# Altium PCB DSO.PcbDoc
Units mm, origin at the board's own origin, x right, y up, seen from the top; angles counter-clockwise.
Board outline 78.7 x 90.25 mm, 2 copper layers (Top Layer, Bottom Layer), stack 1.571 mm thick; 0 components, 80 nets, 1 pads, 0 vias.
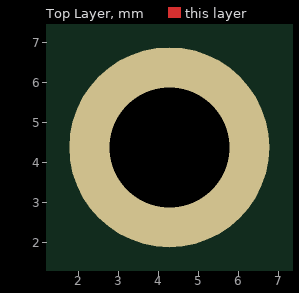
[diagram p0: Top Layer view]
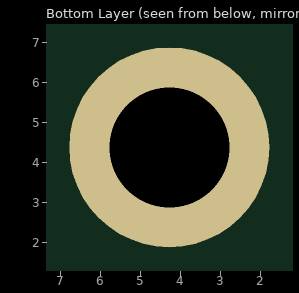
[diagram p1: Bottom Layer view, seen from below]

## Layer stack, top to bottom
Top Solder: solder mask 0.0102, Solder Resist, Dk 3.5
Top Layer: signal copper 0.0356
Dielectric1: core 1.5, FR-4, Dk 4.8
Bottom Layer: signal copper 0.0356
Bottom Solder: solder mask 0.0102, Solder Resist, Dk 3.5

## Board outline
-0.03,0.097 -0.03,90.064 cw(c0.097,90.064) 0.026,90.169 cw(c0.131,90.097) 0.131,90.225 78.54,90.225 cw(c78.54,90.097) 78.668,90.097 78.668,0.097 cw(c78.54,0.097) 78.54,-0.03 0.097,-0.03 cw(c0.097,0.097)

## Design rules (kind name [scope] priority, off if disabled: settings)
Clearance [All] p1: gap=0.254 ignorepadtopadclearanceinfootprint=FALSE except(0: Arc-Hole Track-Hole SMDPad-Hole THPad-Hole Via-Hole Fill-Hole Poly-Hole Region-Hole Text-Hole)
ComponentClearance [All] p1 off: gap=0.254 collisioncheckmode=3 verticalgap=0.254 showdistances=FALSE
DiffPairsRouting [All] p1: maxlimit=0.508 minlimit=0.254 mostfreqgap=0.254 toplayer_minwidth=0.381 toplayer_maxwidth=0.381 toplayer_prefwidth=0.381 bottomlayer_minwidth=0.381 bottomlayer_maxwidth=0.381 bottomlayer_prefwidth=0.381 maxuncoupledlength=12.7
FabricationTestPointUsage TestPointUsage [All] p1: valid=0 allowmultiple=FALSE
FabricationTestpoint Testpoint [All] p1: side=3 testpointundercomponent=TRUE minsize=1.016 maxsize=2.54 preferedsize=1.524 minholesize=0 maxholesize=1.016 preferedholesize=0.813 testpointgrid=0.025 allowsidetop=TRUE allowsidebottom=TRUE usegrid=TRUE gridtolerance=0
Height [All] p1: minheight=0 maxheight=200 prefheight=12.7
HoleSize [All] p1: absolutevalues=TRUE maxlimit=5.055 minlimit=0.381 maxpercent=80.000 minpercent=20.000
MinimumAnnularRing [All] p1: minimumring=0.127
PolygonConnect PolygonConnect_2 [(ObjectKind = 'Via') vs IsNamedPolygon('Bottom Layer-No Net') Or  IsNamedPolygon('Top Power') Or  IsNamedPolygon('TOP MCU VCC') Or  IsNamedPolygon('Top Analog') Or  IsNamedPolygon('Top USB') Or  IsNamedPolygon('Top Digital') Or  IsNamedPolygon('Top RAM VCC') Or  IsNamedPolygon('Bottom Power') Or  IsNamedPolygon('Bottom Analog') Or  IsNamedPolygon('Bottom Digital')] p1: connectstyle=Direct reliefconductorwidth=0.254 reliefentries=4 polygonreliefangle="90 Angle" airgapwidth=0.254
PolygonConnect PolygonConnect_1 [(ObjectKind = 'Via')] p2 off: connectstyle=Direct reliefconductorwidth=0.254 reliefentries=4 polygonreliefangle="90 Angle" airgapwidth=0.254
PolygonConnect [All] p3 off: connectstyle=Relief reliefconductorwidth=0.254 reliefentries=4 polygonreliefangle="90 Angle" airgapwidth=0.254
RoutingVias [All] p1: holewidth=0.381 width=0.635 viastyle="Through Hole" minholewidth=0.381 minwidth=0.635 maxholewidth=2.032 maxwidth=2.54
SilkToSolderMaskClearance SilkscreenOverComponentPads [IsPad] p1: minsilkscreentomaskgap=0.254 clearancetoexposedcopper=TRUE
SolderMaskExpansion [All] p1: expansion=0.152
Width [All] p1: maxlimit=25.4 minlimit=0.152 preferedwidth=0.254 minimp=50.000000 maximp=50.000000 favimp=50.000000
23 further rules are at their usual default settings.

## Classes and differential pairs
net class ADC_D[0..7]: ADC_D0 ADC_D1 ADC_D2 ADC_D3 ADC_D4 ADC_D5 ADC_D6 ADC_D7
net class ADC_A[0..15]: ADC_A0 ADC_A1 ADC_A2 ADC_A3 ADC_A4 ADC_A5 ADC_A6 ADC_A7 ADC_A8 ADC_A9 ADC_A10 ADC_A11 ADC_A12 ADC_A13 ADC_A14 ADC_A15

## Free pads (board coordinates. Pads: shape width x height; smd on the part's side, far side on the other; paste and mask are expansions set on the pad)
  round 5 hole 3: ""(4.267,4.369)

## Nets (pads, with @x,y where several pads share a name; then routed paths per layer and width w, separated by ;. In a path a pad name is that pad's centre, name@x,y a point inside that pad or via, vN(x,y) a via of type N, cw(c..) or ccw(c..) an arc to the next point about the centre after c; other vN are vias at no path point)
3V3: 
ADC_A0: 
ADC_A1: 
ADC_A2: 
ADC_A3: 
ADC_A4: 
ADC_A5: 
ADC_A6: 
ADC_A7: 
ADC_A8: 
ADC_A9: 
ADC_A10: 
ADC_A11: 
ADC_A12: 
ADC_A13: 
ADC_A14: 
ADC_A15: 
ADC_CLK: 
ADC_D0: 
ADC_D1: 
ADC_D2: 
ADC_D3: 
ADC_D4: 
ADC_D5: 
ADC_D6: 
ADC_D7: 
CH1_NORM: 
CLEAR_COUNT: 
COUNTER_CLK: 
CPLD_TCK: 
CPLD_TD0: 
CPLD_TDI: 
CPLD_TMS: 
DGND: 
DVCC: 
ENABLE_COUNT: 
FILL_COMP: 
FULL: 
GND: 
NetC?_1: 
NetD?_K: 
NetTP?_1: 
NetU?_1: 
NetU?_2: 
NetU?_3: 
NetU?_4: 
NetU?_5: 
NetU?_6: 
NetU?_7: 
NetU?_8: 
NetU?_9: 
NetU?_12: 
NetU?_25: 
NetU?_28: 
NetU?_41: 
NetU?_43: 
NetU?_44: 
OVERFLOW: 
R\A\M\_\R\E\A\D\: 
RST: 
RX: 
RX_ISO: 
RXLED: 
SCK: 
SDA: 
SLA: 
TCK: 
TDI: 
TDO: 
TMS: 
TX: 
TX_ISO: 
TXLED: 
USBD+: 
USBD-: 
USBGND: 
USBVCC: 
VCC: 
XTAL1: 
XTAL2: 

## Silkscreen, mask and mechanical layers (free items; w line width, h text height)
Mechanical 1:
  lines w0.254: 0.072,0.021 110.072,0.021 110.072,100.021 0.072,100.021 0.072,0.021 ; 0.123,0.047 110.123,0.047 110.123,100.047 0.123,100.047 0.123,0.047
